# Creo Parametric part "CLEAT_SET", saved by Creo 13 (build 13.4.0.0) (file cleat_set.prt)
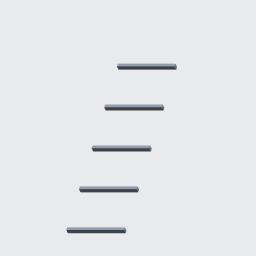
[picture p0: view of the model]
Units: millimeter Newton Second (mmNs); MM, TONNE, SECS

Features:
  1. datum plane "RIGHT"
  2. datum plane "TOP"
  3. datum plane "FRONT"
  4. coordinate system
  5. pattern
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
Surfaces: 30 plane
